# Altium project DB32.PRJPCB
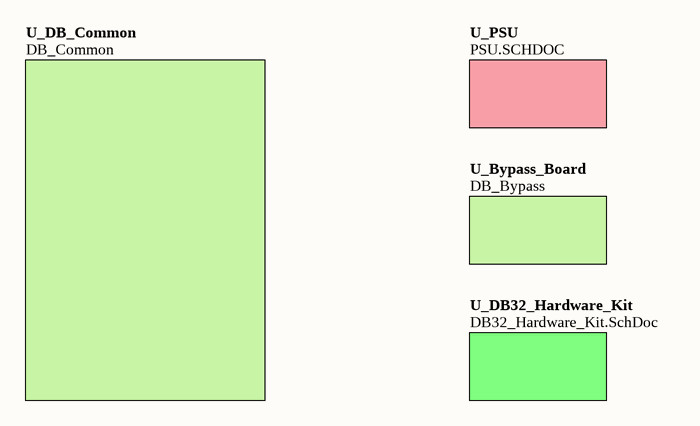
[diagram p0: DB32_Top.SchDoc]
ProjectAddress1: L3, 12A Rodborough Road; ProjectAddress2: Frenchs Forest; ProjectAddress3: NSW 2086; ProjectAddress4: Australia; ProjectAssyNum: D-820-0006; ProjectOrganization: Altium Limited; ProjectRevision: 08; ProjectTitle: DB32 - Daughter Board Lattice; ProjectTotalSheets: 19
8 sheets, 129 parts. Net scope: hierarchical (ports join the sheet entries above them; power ports are global).
Board files: DB32.PcbDoc, DB32_Panel.PcbDoc
Sheets:
  DB32_Top.SchDoc
    U_PSU = PSU.SCHDOC
    U_DB32_Hardware_Kit = DB32_Hardware_Kit.SchDoc
  DEVICES.SchDoc
    U_FPGA = FPGA.SCHDOC
      U_FPGA_Power = FPGA_NonIO.SchDoc
      U_Bypass_3V3 = Bypass_FPGA_3V3.SchDoc
      U_Bypass_1V2 = Bypass_FPGA_1V2.SCHDOC

## Sheet DB32_Top.SchDoc: DB32 Top Level
size A4; Organization: Altium Limited.; Address1: Level 3, 12a Rodborough Rd; Address2: Frenchs Forest 2086; Address3: NSW; Address4: AUSTRALIA; DocumentNumber: 1; SheetNumber: 2; SheetTotal: 21

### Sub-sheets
U_Bypass_Board = DB_Bypass (file not in this document): no entries
U_DB32_Hardware_Kit = DB32_Hardware_Kit.SchDoc: no entries
U_DB_Common = DB_Common (file not in this document): no entries
U_PSU = PSU.SCHDOC: no entries

## Sheet PSU.SCHDOC: Power Supply Top Level
size A4; Organization: Altium Limited.; Address1: Level 3, 12a Rodborough Rd; Address2: Frenchs Forest 2086; Address3: NSW; Address4: AUSTRALIA; DocumentNumber: 9; SheetNumber: 9; SheetTotal: 21
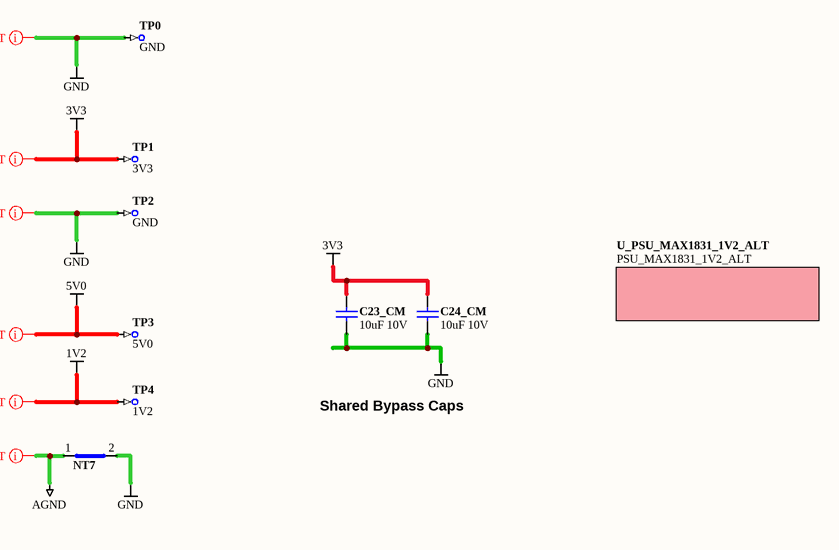
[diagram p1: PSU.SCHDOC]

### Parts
C23_CM  10uF 10V  [CAPC2012-STAR]
C24_CM  10uF 10V  [CAPC2012-STAR]
NT7  Net Tie SMT2  [NETTIE-SMT2-8X8]  (value not drawn)  (net tie, no BOM)
TP0  GND  [TestPin]  (no BOM)
TP1  3V3  [TestPin]  (no BOM)
TP2  GND  [TestPin]  (no BOM)
TP3  5V0  [TestPin]  (no BOM)
TP4  1V2  [TestPin]  (no BOM)

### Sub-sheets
U_PSU_MAX1831_1V2_ALT = PSU_MAX1831_1V2_ALT (file not in this document): no entries

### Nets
1V2: TP4.1
3V3: C23_CM.1 C24_CM.1 TP1.1
5V0: TP3.1
AGND: NT7.1(Net1)
GND: C23_CM.2 C24_CM.2 NT7.2(Net2) TP0.1 TP2.1

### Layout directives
net class PWRNET: 1V2, 3V3, 5V0, AGND, GND

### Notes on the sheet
- Shared Bypass Caps

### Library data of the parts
C23_CM C24_CM = D-101-0087: Capacitor, Ceramic, 10uF 10% 10V 0805 (2012) X5R; Polarity: Non-Polarized
NT7 = D-002-0002: Net-Tie, Surface Mount, 2 x 0.4mm x 0.2mm SMT Pads - For 0.2mm Track
TP0-TP4 = D-006-0000: Test Point, PCB Mount with Silkscreen Box

## Sheet DB32_Hardware_Kit.SchDoc: DB32 Hardware Kit
size A4; Organization: Altium Limited.; Address1: Level 3, 12a Rodborough Rd; Address2: Frenchs Forest 2086; Address3: NSW; Address4: AUSTRALIA; DocumentNumber: 8; SheetNumber: 8; SheetTotal: 21
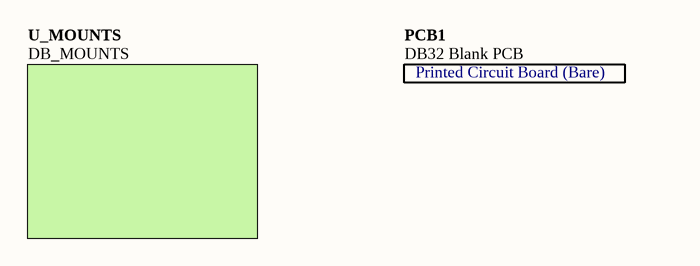
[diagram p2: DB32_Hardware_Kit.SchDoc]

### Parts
PCB1  DB32 Blank PCB  (mechanical)

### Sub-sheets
U_MOUNTS = DB_MOUNTS (file not in this document): no entries

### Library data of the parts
PCB1 = D-810-0006: DB32 Blank PCB - Daughter Board Lattice ECP LFECP33E-3FN672C; ProjectPath: DB32.PrjPCB

## Sheet DEVICES.SchDoc: FPGA, LEDs and SRAM Memory
size A4; Organization: Altium Limited.; Address1: Level 3, 12a Rodborough Rd; Address2: Frenchs Forest 2086; Address3: NSW; Address4: AUSTRALIA; DocumentNumber: 2; SheetNumber: 3; SheetTotal: 21
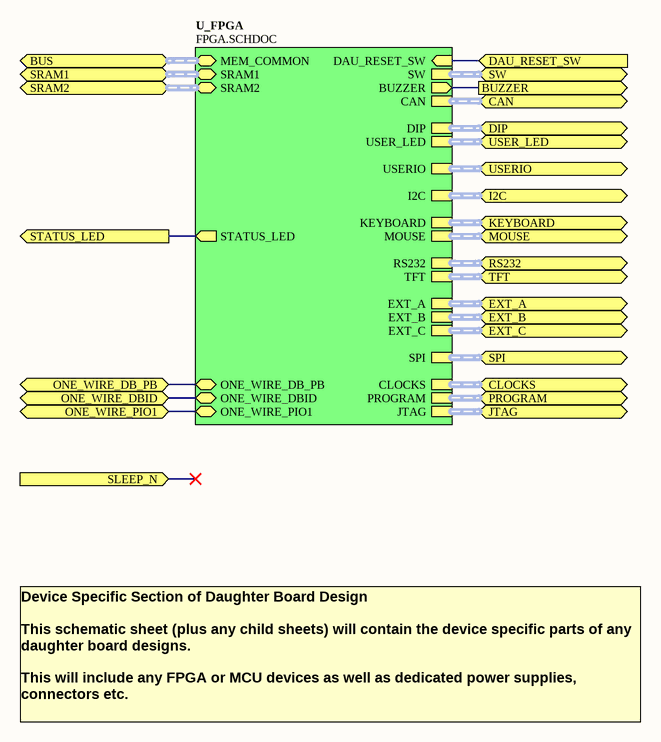
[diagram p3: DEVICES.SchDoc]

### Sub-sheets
U_FPGA = FPGA.SCHDOC: SRAM1 (harness SRAM-256Kx16), SRAM2 (harness SRAM-256Kx16), MEM_COMMON (harness HOSTMEMORY), DAU_RESET_SW (in), BUZZER (out), ONE_WIRE_DBID (bidir), ONE_WIRE_DB_PB (bidir), ONE_WIRE_PIO1 (bidir), JTAG (harness HardSoft_JTAG), SW (harness SW5), DIP (harness SW8), USERIO (harness IO36), EXT_A (harness PBIO), EXT_B (harness PBIO), EXT_C (harness PBIO), USER_LED (harness LED8), SPI (harness DAU_SPI), I2C (harness I2C), CAN (harness CAN_INT), RS232 (harness RS232_INT), KEYBOARD (harness PS2), MOUSE (harness PS2), TFT (harness DAU_TFT), PROGRAM (harness DAU_CTRL), CLOCKS (harness DAU_CLK), STATUS_LED (out)

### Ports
BUS (harness HOSTMEMORY), BUZZER (out), CAN, CLOCKS, DAU_RESET_SW (in), DIP, EXT_A, EXT_B, EXT_C, I2C, JTAG, KEYBOARD, MOUSE, ONE_WIRE_DB_PB (bidir), ONE_WIRE_DBID (bidir), ONE_WIRE_PIO1 (bidir), PROGRAM, RS232, SLEEP_N (in), SPI, SRAM1, SRAM2 (harness SRAM-256Kx16), STATUS_LED (out), SW, TFT, USER_LED, USERIO

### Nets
BUZZER: port BUZZER, sheet U_FPGA/BUZZER
DAU_RESET_SW: port DAU_RESET_SW, sheet U_FPGA/DAU_RESET_SW
ONE_WIRE_DB_PB: port ONE_WIRE_DB_PB, sheet U_FPGA/ONE_WIRE_DB_PB
ONE_WIRE_DBID: port ONE_WIRE_DBID, sheet U_FPGA/ONE_WIRE_DBID
ONE_WIRE_PIO1: port ONE_WIRE_PIO1, sheet U_FPGA/ONE_WIRE_PIO1
STATUS_LED: port STATUS_LED, sheet U_FPGA/STATUS_LED

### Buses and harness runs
harness port BUS = sheet U_FPGA/MEM_COMMON
harness port CAN = sheet U_FPGA/CAN
harness port CLOCKS = sheet U_FPGA/CLOCKS
harness port DIP = sheet U_FPGA/DIP
harness port EXT_A = sheet U_FPGA/EXT_A
harness port EXT_B = sheet U_FPGA/EXT_B
harness port EXT_C = sheet U_FPGA/EXT_C
harness port I2C = sheet U_FPGA/I2C
harness port JTAG = sheet U_FPGA/JTAG
harness port KEYBOARD = sheet U_FPGA/KEYBOARD
harness port MOUSE = sheet U_FPGA/MOUSE
harness port PROGRAM = sheet U_FPGA/PROGRAM
harness port RS232 = sheet U_FPGA/RS232
harness port SPI = sheet U_FPGA/SPI
harness port SRAM1 = sheet U_FPGA/SRAM1
harness port SRAM2 = sheet U_FPGA/SRAM2
harness port SW = sheet U_FPGA/SW
harness port TFT = sheet U_FPGA/TFT
harness port USER_LED = sheet U_FPGA/USER_LED
harness port USERIO = sheet U_FPGA/USERIO

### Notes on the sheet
- Device Specific Section of Daughter Board Design
  This schematic sheet (plus any child sheets) will contain the device specific parts of any daughter board designs.
  This will include any FPGA or MCU devices as well as dedicated power supplies, connectors etc.

## Sheet FPGA.SCHDOC: FPGA Connections
size A2; Organization: Altium Limited.; Address1: Level 3, 12a Rodborough Rd; Address2: Frenchs Forest 2086; Address3: NSW; Address4: AUSTRALIA; DocumentNumber: 3; SheetNumber: 4; SheetTotal: 21; PageSetup: Record=PageOptions|CenterHorizontal=True|CenterVertical=True|PrintScale=0.49|XCorrection=1.00|YCorrection=1.00|PrintKind=2|BorderSize=5000000|LeftOffset=0|BottomOffset=0|Orientation=2|PaperLength=1000|PaperWidth=1000|Scale=100|PaperSource=15|PrintQuality=600|MediaType=1|DitherType=10|PaperKind=A4|PrintScaleMode=1
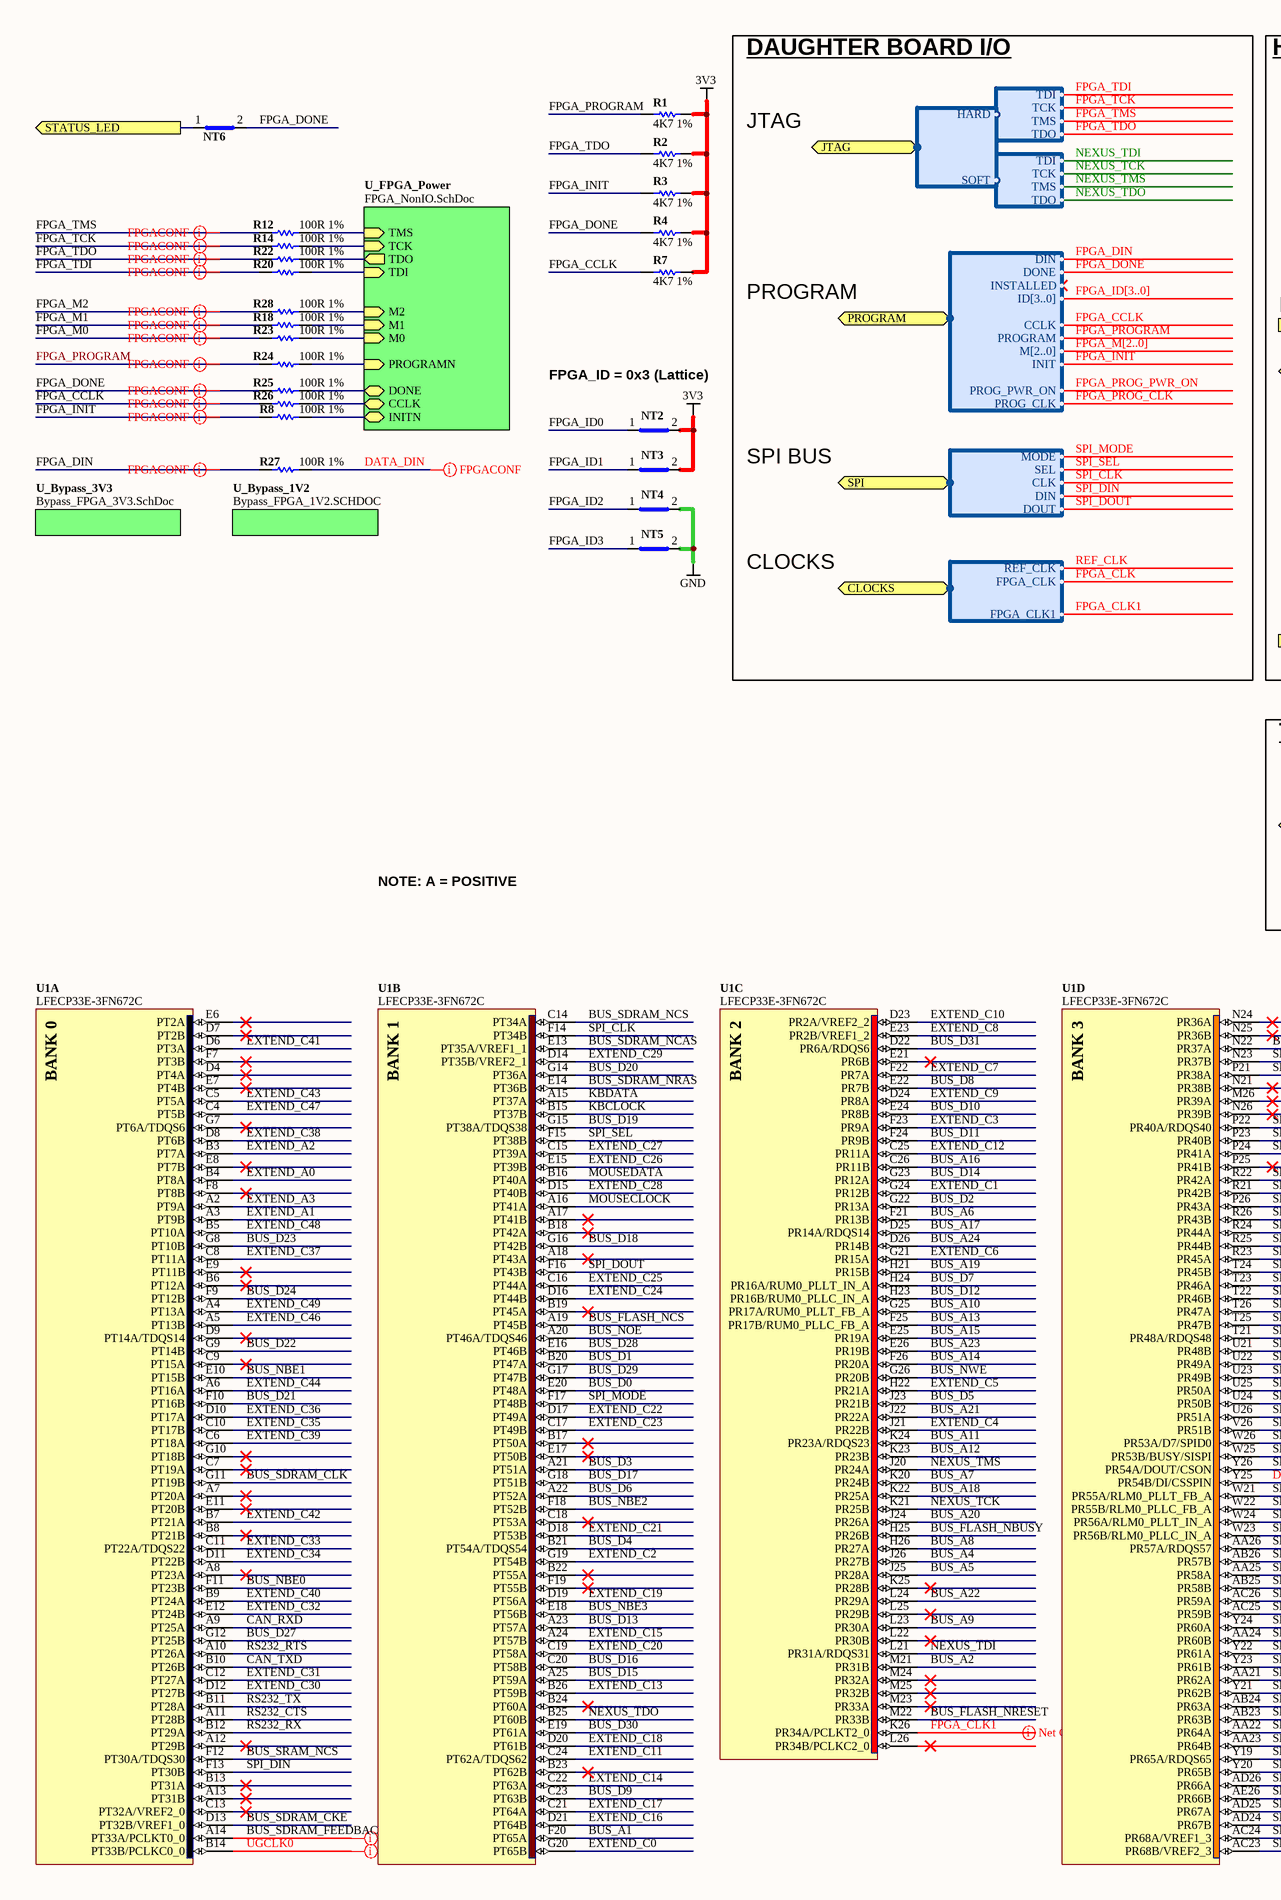
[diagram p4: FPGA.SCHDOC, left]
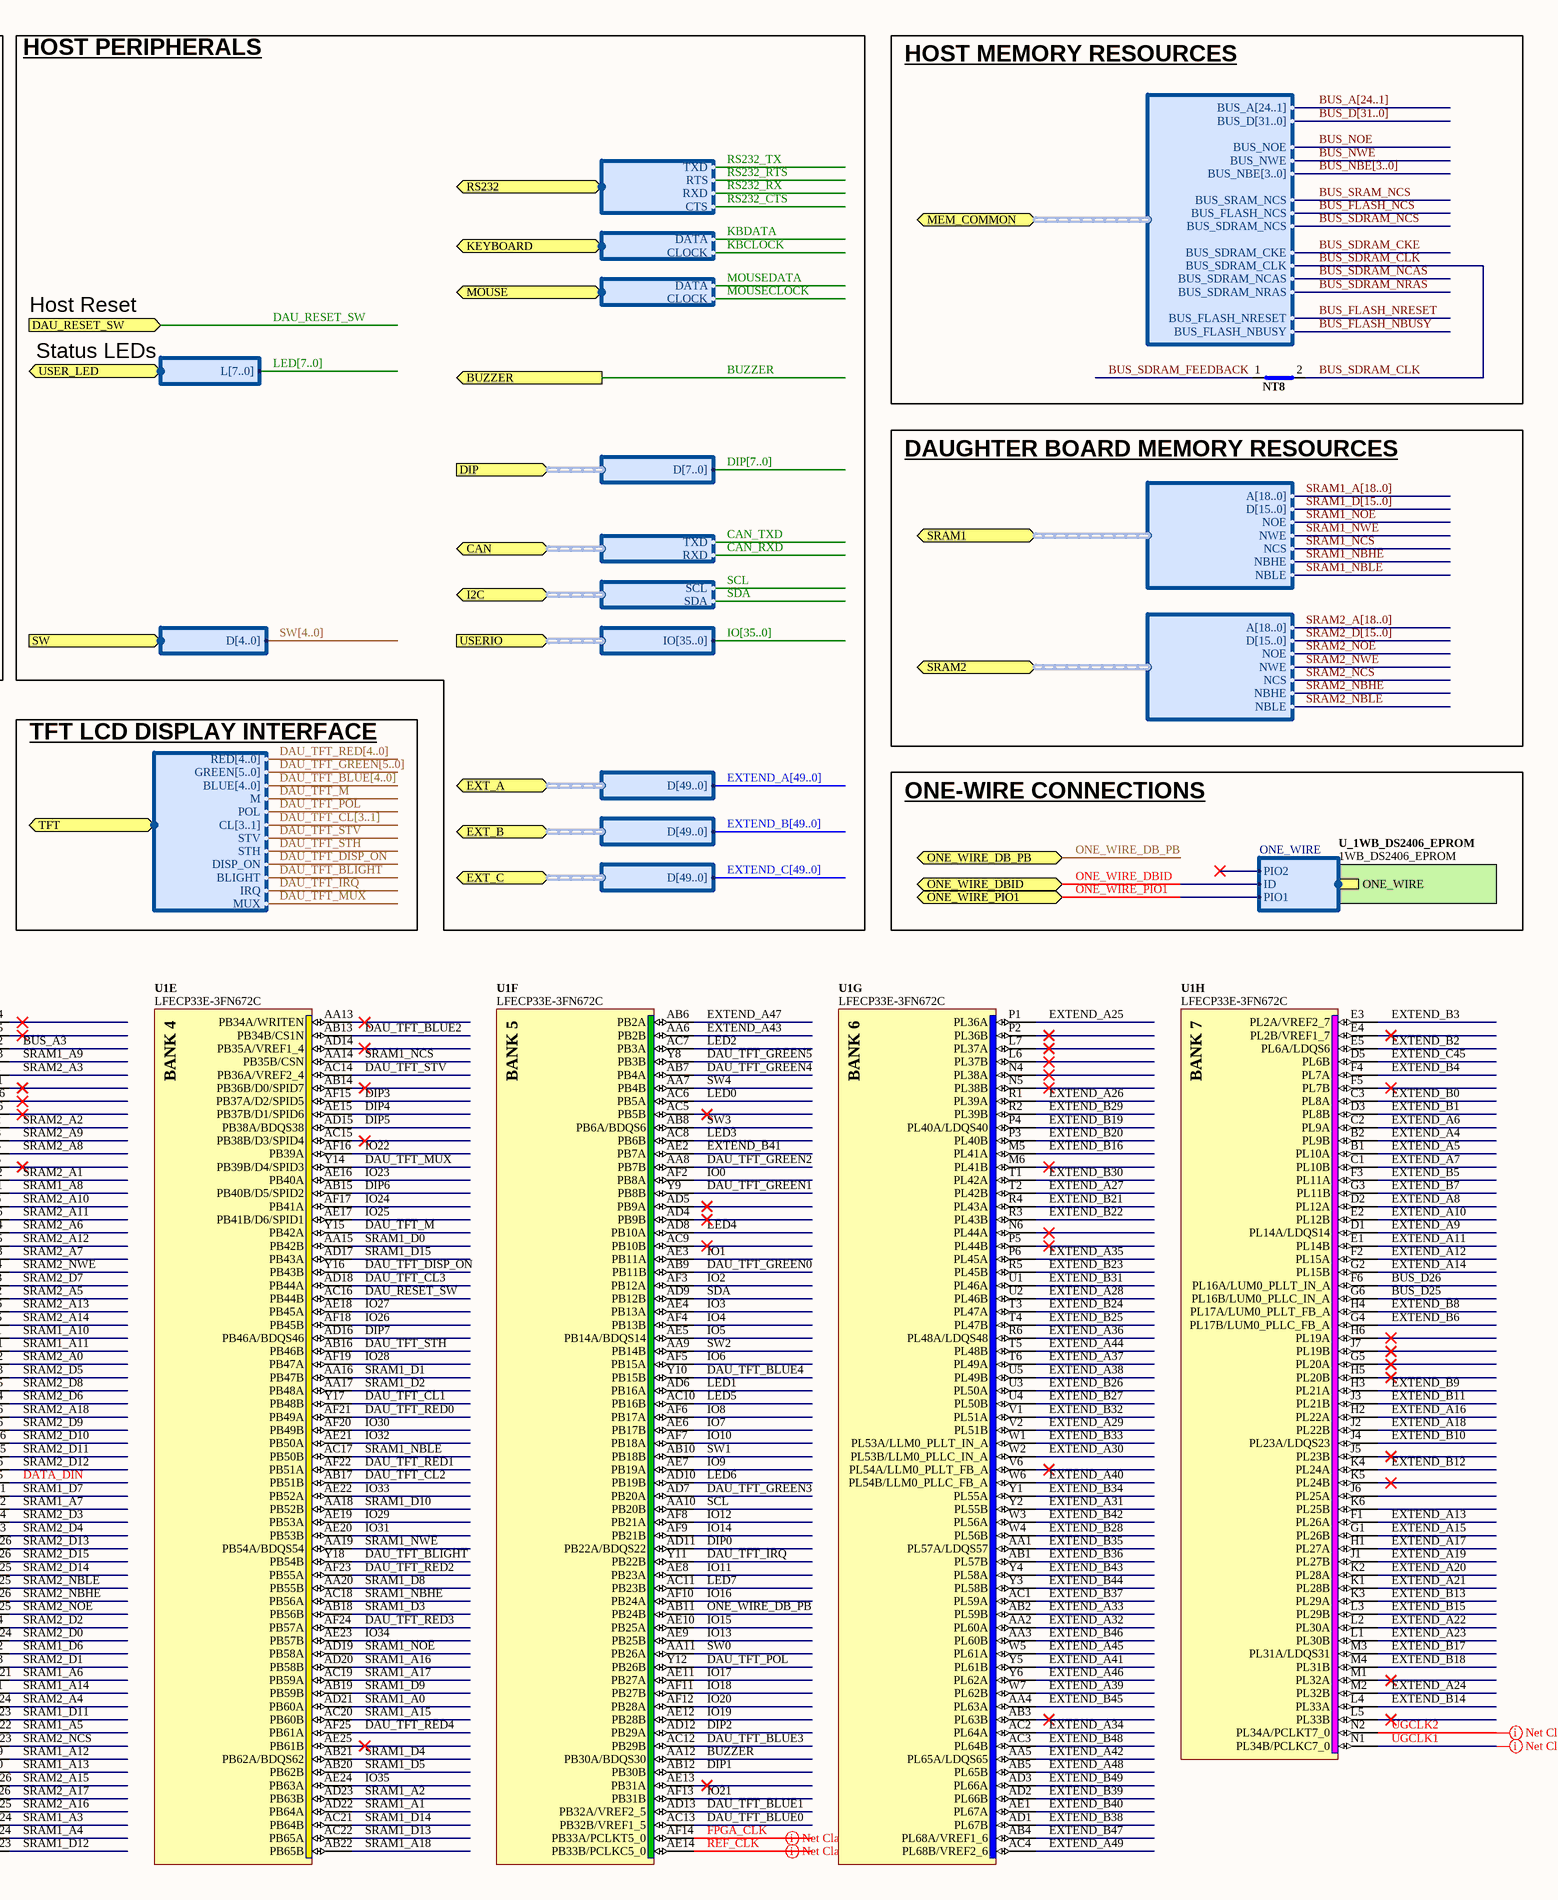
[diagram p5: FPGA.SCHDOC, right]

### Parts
NT2  Net Tie SMT2  [NETTIE-SMT2-8X8]  (value not drawn)  (net tie, no BOM)
NT3  Net Tie SMT2  [NETTIE-SMT2-8X8]  (value not drawn)  (net tie, no BOM)
NT4  Net Tie SMT2  [NETTIE-SMT2-8X8]  (value not drawn)  (net tie, no BOM)
NT5  Net Tie SMT2  [NETTIE-SMT2-8X8]  (value not drawn)  (net tie, no BOM)
NT6  Net Tie SMT2  [NETTIE-SMT2-8X8]  (value not drawn)  (net tie, no BOM)
NT8  Net Tie SMT2  [NETTIE-SMT2-8X8]  (value not drawn)  (net tie, no BOM)
R1  4K7 1%  [RESC1005-STAR]
R2  4K7 1%  [RESC1005-STAR]
R3  4K7 1%  [RESC1005-STAR]
R4  4K7 1%  [RESC1005-STAR]
R7  4K7 1%  [RESC1005-STAR]
R8  100R 1%  [RESC1005-STAR]
R12  100R 1%  [RESC1005-STAR]
R14  100R 1%  [RESC1005-STAR]
R18  100R 1%  [RESC1005-STAR]
R20  100R 1%  [RESC1005-STAR]
R22  100R 1%  [RESC1005-STAR]
R23  100R 1%  [RESC1005-STAR]
R24  100R 1%  [RESC1005-STAR]
R25  100R 1%  [RESC1005-STAR]
R26  100R 1%  [RESC1005-STAR]
R27  100R 1%  [RESC1005-STAR]
R28  100R 1%  [RESC1005-STAR]
U1  LFECP33E-3FN672C  [BGA100P26X26-672]  (parts A,B,C,D,E,F,G,H of 12)

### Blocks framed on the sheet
HOST MEMORY RESOURCES: NT8

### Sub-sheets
U_1WB_DS2406_EPROM = 1WB_DS2406_EPROM (file not in this document): ONE_WIRE (harness ONE_WIRE)
U_Bypass_1V2 = Bypass_FPGA_1V2.SCHDOC: no entries
U_Bypass_3V3 = Bypass_FPGA_3V3.SchDoc: no entries
U_FPGA_Power = FPGA_NonIO.SchDoc: TMS (in), DONE (bidir), M1 (in), CCLK (bidir), M0 (in), M2 (in), TCK (in), INITN (bidir), TDI (in), PROGRAMN (in), TDO (out)

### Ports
BUZZER (out), CAN (harness CAN_INT), CLOCKS (harness DAU_CLK), DAU_RESET_SW (in), DIP (harness SW8), EXT_A (harness PBIO), EXT_B (harness PBIO), EXT_C (harness PBIO), I2C (harness I2C), JTAG (harness HARDSOFT_JTAG), KEYBOARD (harness PS2), MEM_COMMON (harness HOSTMEMORY), MOUSE (harness PS2), ONE_WIRE_DB_PB (bidir), ONE_WIRE_DBID (bidir), ONE_WIRE_PIO1 (bidir), PROGRAM (harness DAU_CTRL), RS232 (harness RS232_INT), SPI (harness DAU_SPI), SRAM1 (harness SRAM-256Kx16), SRAM2 (harness SRAM-256Kx16), STATUS_LED (out), SW (harness SW5), TFT (harness DAU_TFT), USER_LED (harness LED8), USERIO (harness IO36)

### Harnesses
ONE_WIRE: ID, PIO1, PIO2
SRAM-256Kx16: A[18..0], D[15..0], NCS, NWE, NOE, NBHE, NBLE
HOSTMEMORY: BUS_A[24..1], BUS_D[31..0], BUS_NOE, BUS_NWE, BUS_NBE[3..0], BUS_SRAM_NCS, BUS_FLASH_NCS, BUS_SDRAM_NCS, BUS_SDRAM_CKE, BUS_SDRAM_CLK, BUS_SDRAM_NCAS, BUS_SDRAM_NRAS, BUS_FLASH_NRESET, BUS_FLASH_NBUSY
DAU_CLK: REF_CLK, FPGA_CLK, FPGA_CLK1
DAU_SPI: MODE, SEL, CLK, DIN, DOUT
DAU_CTRL: DIN, DONE, INSTALLED, ID[3..0], CCLK, PROGRAM, M[2..0], INIT, PROG_PWR_ON, PROG_CLK
JTAG: TMS, TDO, TDI, TCK
HARDSOFT_JTAG: HARD, SOFT
LED8: L[7..0]
SW5: D[4..0]
DAU_TFT: RED[4..0], GREEN[5..0], BLUE[4..0], M, POL, CL[3..1], STV, STH, DISP_ON, BLIGHT, IRQ, MUX
PS2: DATA, CLOCK
RS232_INT: RXD, TXD, RTS, CTS
IO36: IO[35..0]
SW8: D[7..0]
CAN_INT: TXD, RXD
I2C: SCL, SDA
PBIO: D[49..0]

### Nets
3V3: NT2.2(Net2) NT3.2(Net2) R1.2 R2.2 R3.2 R4.2 R7.2
GND: NT4.2(Net2) NT5.2(Net2)
BUS_A1: U1.F20(PT65A)
BUS_A2: U1.M21(PR31B)
BUS_A3: U1.N22(PR37A)
BUS_A4: U1.J26(PR27B)
BUS_A5: U1.J25(PR28A)
BUS_A6: U1.F21(PR13B)
BUS_A7: U1.K20(PR24B)
BUS_A8: U1.H26(PR27A)
BUS_A9: U1.L23(PR30A)
BUS_A10: U1.G25(PR17A/RUM0_PLLT_FB_A)
BUS_A11: U1.K24(PR23A/RDQS23)
BUS_A12: U1.K23(PR23B)
BUS_A13: U1.F25(PR17B/RUM0_PLLC_FB_A)
BUS_A14: U1.F26(PR20A)
BUS_A15: U1.E25(PR19A)
BUS_A16: U1.C26(PR11B)
BUS_A17: U1.D25(PR14A/RDQS14)
BUS_A18: U1.K22(PR25A)
BUS_A19: U1.H21(PR15B)
BUS_A20: U1.J24(PR26A)
BUS_A21: U1.J22(PR22A)
BUS_A22: U1.L24(PR29A)
BUS_A23: U1.E26(PR19B)
BUS_A24: U1.D26(PR14B)
BUS_D0: U1.E20(PT48A)
BUS_D1: U1.B20(PT47A)
BUS_D2: U1.G22(PR13A)
BUS_D3: U1.A21(PT51A)
BUS_D4: U1.B21(PT54A/TDQS54)
BUS_D5: U1.J23(PR21B)
BUS_D6: U1.A22(PT52A)
BUS_D7: U1.H24(PR16A/RUM0_PLLT_IN_A)
BUS_D8: U1.E22(PR7B)
BUS_D9: U1.C23(PT63B)
BUS_D10: U1.E24(PR8B)
BUS_D11: U1.F24(PR9B)
BUS_D12: U1.H23(PR16B/RUM0_PLLC_IN_A)
BUS_D13: U1.A23(PT57A)
BUS_D14: U1.G23(PR12A)
BUS_D15: U1.A25(PT59A)
BUS_D16: U1.C20(PT58B)
BUS_D17: U1.G18(PT51B)
BUS_D18: U1.G16(PT42B)
BUS_D19: U1.G15(PT38A/TDQS38)
BUS_D20: U1.G14(PT36A)
BUS_D21: U1.F10(PT16B)
BUS_D22: U1.G9(PT14B)
BUS_D23: U1.G8(PT10B)
BUS_D24: U1.F9(PT12B)
BUS_D25: U1.G6(PL16B/LUM0_PLLC_IN_A)
BUS_D26: U1.F6(PL16A/LUM0_PLLT_IN_A)
BUS_D27: U1.G12(PT25B)
BUS_D28: U1.E16(PT46B)
BUS_D29: U1.G17(PT47B)
BUS_D30: U1.E19(PT61A)
BUS_D31: U1.D22(PR6A/RDQS6)
BUS_FLASH_NBUSY: U1.H25(PR26B) ; port MEM_COMMON.BUS_FLASH_NBUSY
BUS_FLASH_NCS: U1.A19(PT45B) ; port MEM_COMMON.BUS_FLASH_NCS
BUS_FLASH_NRESET: U1.M22(PR33B) ; port MEM_COMMON.BUS_FLASH_NRESET
BUS_NBE0: U1.F11(PT23B)
BUS_NBE1: U1.E10(PT15B)
BUS_NBE2: U1.F18(PT52B)
BUS_NBE3: U1.E18(PT56B)
BUS_NOE: U1.A20(PT46A/TDQS46) ; port MEM_COMMON.BUS_NOE
BUS_NWE: U1.G26(PR20B) ; port MEM_COMMON.BUS_NWE
BUS_SDRAM_CKE: U1.D13(PT32B/VREF1_0) ; port MEM_COMMON.BUS_SDRAM_CKE
BUS_SDRAM_CLK: NT8.2(Net2) U1.G11(PT19B) ; port MEM_COMMON.BUS_SDRAM_CLK
BUS_SDRAM_FEEDBACK: NT8.1(Net1) U1.A14(PT33A/PCLKT0_0)
BUS_SDRAM_NCAS: U1.E13(PT35A/VREF1_1) ; port MEM_COMMON.BUS_SDRAM_NCAS
BUS_SDRAM_NCS: U1.C14(PT34A) ; port MEM_COMMON.BUS_SDRAM_NCS
BUS_SDRAM_NRAS: U1.E14(PT36B) ; port MEM_COMMON.BUS_SDRAM_NRAS
BUS_SRAM_NCS: U1.F12(PT30A/TDQS30) ; port MEM_COMMON.BUS_SRAM_NCS
BUZZER: U1.AA12(PB30A/BDQS30) ; port BUZZER
CAN_RXD: U1.A9(PT25A) ; port CAN.RXD
CAN_TXD: U1.B10(PT26B) ; port CAN.TXD
CCLK: R26.2 ; sheet U_FPGA_Power/CCLK
DATA_DIN: R27.2 U1.Y25(PR54B/DI/CSSPIN)
DAU_RESET_SW: U1.AC16(PB44B) ; port DAU_RESET_SW
DAU_TFT_BLIGHT: U1.Y18(PB54B) ; port TFT.BLIGHT
DAU_TFT_BLUE0: U1.AC13(PB32B/VREF1_5)
DAU_TFT_BLUE1: U1.AD13(PB32A/VREF2_5)
DAU_TFT_BLUE2: U1.AB13(PB34B/CS1N)
DAU_TFT_BLUE3: U1.AC12(PB29B)
DAU_TFT_BLUE4: U1.Y10(PB15B)
DAU_TFT_CL1: U1.Y17(PB48B)
DAU_TFT_CL2: U1.AB17(PB51B)
DAU_TFT_CL3: U1.AD18(PB44A)
DAU_TFT_DISP_ON: U1.Y16(PB43B) ; port TFT.DISP_ON
DAU_TFT_GREEN0: U1.AB9(PB11B)
DAU_TFT_GREEN1: U1.Y9(PB8B)
DAU_TFT_GREEN2: U1.AA8(PB7B)
DAU_TFT_GREEN3: U1.AD7(PB20A)
DAU_TFT_GREEN4: U1.AB7(PB4A)
DAU_TFT_GREEN5: U1.Y8(PB3B)
DAU_TFT_IRQ: U1.Y11(PB22B) ; port TFT.IRQ
DAU_TFT_M: U1.Y15(PB42A) ; port TFT.M
DAU_TFT_MUX: U1.Y14(PB39B/D4/SPID3) ; port TFT.MUX
DAU_TFT_POL: U1.Y12(PB26B) ; port TFT.POL
DAU_TFT_RED0: U1.AF21(PB49A)
DAU_TFT_RED1: U1.AF22(PB51A)
DAU_TFT_RED2: U1.AF23(PB55A)
DAU_TFT_RED3: U1.AF24(PB57A)
DAU_TFT_RED4: U1.AF25(PB61A)
DAU_TFT_STH: U1.AB16(PB46B) ; port TFT.STH
DAU_TFT_STV: U1.AC14(PB36A/VREF2_4) ; port TFT.STV
DIP0: U1.AD11(PB22A/BDQS22)
DIP1: U1.AB12(PB30B)
DIP2: U1.AD12(PB29A)
DIP3: U1.AF15(PB37A/D2/SPID5)
DIP4: U1.AE15(PB37B/D1/SPID6)
DIP5: U1.AD15(PB38A/BDQS38)
DIP6: U1.AB15(PB40B/D5/SPID2)
DIP7: U1.AD16(PB46A/BDQS46)
DONE: R25.2 ; sheet U_FPGA_Power/DONE
EXTEND_A0: U1.B4(PT8A)
EXTEND_A1: U1.A3(PT9B)
EXTEND_A2: U1.B3(PT7A)
EXTEND_A3: U1.A2(PT9A)
EXTEND_A4: U1.B2(PL9B)
EXTEND_A5: U1.B1(PL10A)
EXTEND_A6: U1.C2(PL9A)
EXTEND_A7: U1.C1(PL10B)
EXTEND_A8: U1.D2(PL12A)
EXTEND_A9: U1.D1(PL14A/LDQS14)
EXTEND_A10: U1.E2(PL12B)
EXTEND_A11: U1.E1(PL14B)
EXTEND_A12: U1.F2(PL15A)
EXTEND_A13: U1.F1(PL26A)
EXTEND_A14: U1.G2(PL15B)
EXTEND_A15: U1.G1(PL26B)
EXTEND_A16: U1.H2(PL22A)
EXTEND_A17: U1.H1(PL27A)
EXTEND_A18: U1.J2(PL22B)
EXTEND_A19: U1.J1(PL27B)
EXTEND_A20: U1.K2(PL28A)
EXTEND_A21: U1.K1(PL28B)
EXTEND_A22: U1.L2(PL30A)
EXTEND_A23: U1.L1(PL30B)
EXTEND_A24: U1.M2(PL32B)
EXTEND_A25: U1.P1(PL36A)
EXTEND_A26: U1.R1(PL39A)
EXTEND_A27: U1.T2(PL42B)
EXTEND_A28: U1.U2(PL46B)
EXTEND_A29: U1.V2(PL51B)
EXTEND_A30: U1.W2(PL53B/LLM0_PLLC_IN_A)
EXTEND_A31: U1.Y2(PL55B)
EXTEND_A32: U1.AA2(PL60A)
EXTEND_A33: U1.AB2(PL59B)
EXTEND_A34: U1.AC2(PL64A)
EXTEND_A35: U1.P6(PL45A)
EXTEND_A36: U1.R6(PL48A/LDQS48)
EXTEND_A37: U1.T6(PL49A)
EXTEND_A38: U1.U5(PL49B)
EXTEND_A39: U1.W7(PL62B)
EXTEND_A40: U1.W6(PL54B/LLM0_PLLC_FB_A)
EXTEND_A41: U1.Y5(PL61B)
EXTEND_A42: U1.AA5(PL65A/LDQS65)
EXTEND_A43: U1.AA6(PB2B)
EXTEND_A44: U1.T5(PL48B)
EXTEND_A45: U1.W5(PL61A)
EXTEND_A46: U1.Y6(PL62A)
EXTEND_A47: U1.AB6(PB2A)
EXTEND_A48: U1.AB5(PL65B)
EXTEND_A49: U1.AC4(PL68B/VREF2_6)
EXTEND_B0: U1.C3(PL8A)
EXTEND_B1: U1.D3(PL8B)
EXTEND_B2: U1.E5(PL6A/LDQS6)
EXTEND_B3: U1.E3(PL2A/VREF2_7)
EXTEND_B4: U1.F4(PL7A)
EXTEND_B5: U1.F3(PL11A)
EXTEND_B6: U1.G4(PL17B/LUM0_PLLC_FB_A)
EXTEND_B7: U1.G3(PL11B)
EXTEND_B8: U1.H4(PL17A/LUM0_PLLT_FB_A)
EXTEND_B9: U1.H3(PL21A)
EXTEND_B10: U1.J4(PL23A/LDQS23)
EXTEND_B11: U1.J3(PL21B)
EXTEND_B12: U1.K4(PL24A)
EXTEND_B13: U1.K3(PL29A)
EXTEND_B14: U1.L4(PL33A)
EXTEND_B15: U1.L3(PL29B)
EXTEND_B16: U1.M5(PL41A)
EXTEND_B17: U1.M3(PL31A/LDQS31)
EXTEND_B18: U1.M4(PL31B)
EXTEND_B19: U1.P4(PL40A/LDQS40)
EXTEND_B20: U1.P3(PL40B)
EXTEND_B21: U1.R4(PL43A)
EXTEND_B22: U1.R3(PL43B)
EXTEND_B23: U1.R5(PL45B)
EXTEND_B24: U1.T3(PL47A)
EXTEND_B25: U1.T4(PL47B)
EXTEND_B26: U1.U3(PL50A)
EXTEND_B27: U1.U4(PL50B)
EXTEND_B28: U1.W4(PL56B)
EXTEND_B29: U1.R2(PL39B)
EXTEND_B30: U1.T1(PL42A)
EXTEND_B31: U1.U1(PL46A)
EXTEND_B32: U1.V1(PL51A)
EXTEND_B33: U1.W1(PL53A/LLM0_PLLT_IN_A)
EXTEND_B34: U1.Y1(PL55A)
EXTEND_B35: U1.AA1(PL57A/LDQS57)
EXTEND_B36: U1.AB1(PL57B)
EXTEND_B37: U1.AC1(PL59A)
EXTEND_B38: U1.AD1(PL67B)
EXTEND_B39: U1.AD2(PL66B)
EXTEND_B40: U1.AE1(PL67A)
EXTEND_B41: U1.AE2(PB7A)
EXTEND_B42: U1.W3(PL56A)
EXTEND_B43: U1.Y4(PL58A)
EXTEND_B44: U1.Y3(PL58B)
EXTEND_B45: U1.AA4(PL63A)
EXTEND_B46: U1.AA3(PL60B)
EXTEND_B47: U1.AB4(PL68A/VREF1_6)
EXTEND_B48: U1.AC3(PL64B)
EXTEND_B49: U1.AD3(PL66A)
EXTEND_C0: U1.G20(PT65B)
EXTEND_C1: U1.G24(PR12B)
EXTEND_C2: U1.G19(PT54B)
EXTEND_C3: U1.F23(PR9A)
EXTEND_C4: U1.J21(PR22B)
EXTEND_C5: U1.H22(PR21A)
EXTEND_C6: U1.G21(PR15A)
EXTEND_C7: U1.F22(PR7A)
EXTEND_C8: U1.E23(PR2B/VREF1_2)
EXTEND_C9: U1.D24(PR8A)
EXTEND_C10: U1.D23(PR2A/VREF2_2)
EXTEND_C11: U1.C24(PT62A/TDQS62)
EXTEND_C12: U1.C25(PR11A)
EXTEND_C13: U1.B26(PT59B)
EXTEND_C14: U1.C22(PT63A)
EXTEND_C15: U1.A24(PT57B)
EXTEND_C16: U1.D21(PT64B)
EXTEND_C17: U1.C21(PT64A)
EXTEND_C18: U1.D20(PT61B)
EXTEND_C19: U1.D19(PT56A)
EXTEND_C20: U1.C19(PT58A)
EXTEND_C21: U1.D18(PT53B)
EXTEND_C22: U1.D17(PT49A)
EXTEND_C23: U1.C17(PT49B)
EXTEND_C24: U1.D16(PT44B)
EXTEND_C25: U1.C16(PT44A)
EXTEND_C26: U1.E15(PT39B)
EXTEND_C27: U1.C15(PT39A)
EXTEND_C28: U1.D15(PT40B)
EXTEND_C29: U1.D14(PT35B/VREF2_1)
EXTEND_C30: U1.D12(PT27B)
EXTEND_C31: U1.C12(PT27A)
EXTEND_C32: U1.E12(PT24B)
EXTEND_C33: U1.C11(PT22A/TDQS22)
EXTEND_C34: U1.D11(PT22B)
EXTEND_C35: U1.C10(PT17B)
EXTEND_C36: U1.D10(PT17A)
EXTEND_C37: U1.C8(PT11A)
EXTEND_C38: U1.D8(PT6B)
EXTEND_C39: U1.C6(PT18A)
EXTEND_C40: U1.B9(PT24A)
EXTEND_C41: U1.D6(PT3A)
EXTEND_C42: U1.B7(PT21A)
EXTEND_C43: U1.C5(PT5A)
EXTEND_C44: U1.A6(PT16A)
EXTEND_C45: U1.D5(PL6B)
EXTEND_C46: U1.A5(PT13B)
EXTEND_C47: U1.C4(PT5B)
EXTEND_C48: U1.B5(PT10A)
EXTEND_C49: U1.A4(PT13A)
FPGA_CCLK: R7.1 R26.1 ; port PROGRAM.CCLK
FPGA_CLK: U1.AF14(PB33A/PCLKT5_0) ; port CLOCKS.FPGA_CLK
FPGA_CLK1: U1.K26(PR34A/PCLKT2_0) ; port CLOCKS.FPGA_CLK1
FPGA_DIN: R27.1 ; port PROGRAM.DIN
FPGA_DONE: NT6.2(Net2) R4.1 R25.1 ; port PROGRAM.DONE
FPGA_ID0: NT2.1(Net1)
FPGA_ID1: NT3.1(Net1)
FPGA_ID2: NT4.1(Net1)
FPGA_ID3: NT5.1(Net1)
FPGA_INIT: R3.1 R8.1 ; port PROGRAM.INIT
FPGA_M0: R23.1
FPGA_M1: R18.1
FPGA_M2: R28.1
FPGA_PROGRAM: R1.1 R24.1 ; port PROGRAM.PROGRAM
FPGA_TCK: R14.1 ; harness JTAG.TCK
FPGA_TDI: R20.1 ; harness JTAG.TDI
FPGA_TDO: R2.1 R22.1 ; harness JTAG.TDO
FPGA_TMS: R12.1 ; harness JTAG.TMS
INITN: R8.2 ; sheet U_FPGA_Power/INITN
IO0: U1.AF2(PB8A)
IO1: U1.AE3(PB11A)
IO2: U1.AF3(PB12A)
IO3: U1.AE4(PB13A)
IO4: U1.AF4(PB13B)
IO5: U1.AE5(PB14A/BDQS14)
IO6: U1.AF5(PB15A)
IO7: U1.AE6(PB17B)
IO8: U1.AF6(PB17A)
IO9: U1.AE7(PB19A)
IO10: U1.AF7(PB18A)
IO11: U1.AE8(PB23A)
IO12: U1.AF8(PB21A)
IO13: U1.AE9(PB25B)
IO14: U1.AF9(PB21B)
IO15: U1.AE10(PB25A)
IO16: U1.AF10(PB24A)
IO17: U1.AE11(PB27A)
IO18: U1.AF11(PB27B)
IO19: U1.AE12(PB28B)
IO20: U1.AF12(PB28A)
IO21: U1.AF13(PB31B)
IO22: U1.AF16(PB39A)
IO23: U1.AE16(PB40A)
IO24: U1.AF17(PB41A)
IO25: U1.AE17(PB41B/D6/SPID1)
IO26: U1.AF18(PB45B)
IO27: U1.AE18(PB45A)
IO28: U1.AF19(PB47A)
IO29: U1.AE19(PB53A)
IO30: U1.AF20(PB49B)
IO31: U1.AE20(PB53B)
IO32: U1.AE21(PB50A)
IO33: U1.AE22(PB52A)
IO34: U1.AE23(PB57B)
IO35: U1.AE24(PB63A)
KBCLOCK: U1.B15(PT37B) ; port KEYBOARD.CLOCK
KBDATA: U1.A15(PT37A) ; port KEYBOARD.DATA
LED0: U1.AC6(PB5A)
LED1: U1.AD6(PB16A)
LED2: U1.AC7(PB3A)
LED3: U1.AC8(PB6B)
LED4: U1.AD8(PB10A)
LED5: U1.AC10(PB16B)
LED6: U1.AD10(PB19B)
LED7: U1.AC11(PB23B)
M0: R23.2 ; sheet U_FPGA_Power/M0
M1: R18.2 ; sheet U_FPGA_Power/M1
M2: R28.2 ; sheet U_FPGA_Power/M2
MOUSECLOCK: U1.A16(PT41A) ; port MOUSE.CLOCK
MOUSEDATA: U1.B16(PT40A) ; port MOUSE.DATA
NEXUS_TCK: U1.K21(PR25B) ; harness JTAG.TCK
NEXUS_TDI: U1.L21(PR31A/RDQS31) ; harness JTAG.TDI
NEXUS_TDO: U1.B25(PT60B) ; harness JTAG.TDO
NEXUS_TMS: U1.J20(PR24A) ; harness JTAG.TMS
ONE_WIRE_DB_PB: U1.AB11(PB24B) ; port ONE_WIRE_DB_PB
ONE_WIRE_DBID: port ONE_WIRE_DBID, sheet U_1WB_DS2406_EPROM/ONE_WIRE.ID
ONE_WIRE_PIO1: port ONE_WIRE_PIO1, sheet U_1WB_DS2406_EPROM/ONE_WIRE.PIO1
PROGRAMN: R24.2 ; sheet U_FPGA_Power/PROGRAMN
REF_CLK: U1.AE14(PB33B/PCLKC5_0) ; port CLOCKS.REF_CLK
RS232_CTS: U1.A11(PT28B) ; port RS232.CTS
RS232_RTS: U1.A10(PT26A) ; port RS232.RTS
RS232_RX: U1.B12(PT29A) ; port RS232.RXD
RS232_TX: U1.B11(PT28A) ; port RS232.TXD
SCL: U1.AA10(PB20B) ; port I2C.SCL
SDA: U1.AD9(PB12B) ; port I2C.SDA
SPI_CLK: U1.F14(PT34B) ; port SPI.CLK
SPI_DIN: U1.F13(PT30B) ; port SPI.DIN
SPI_DOUT: U1.F16(PT43B) ; port SPI.DOUT
SPI_MODE: U1.F17(PT48B) ; port SPI.MODE
SPI_SEL: U1.F15(PT38B) ; port SPI.SEL
SRAM1_A0: U1.AD21(PB60A)
SRAM1_A1: U1.AD22(PB64A)
SRAM1_A2: U1.AD23(PB63B)
SRAM1_A3: U1.AD24(PR67B)
SRAM1_A4: U1.AC24(PR68A/VREF1_3)
SRAM1_A5: U1.AA22(PR64A)
SRAM1_A6: U1.AA21(PR62A)
SRAM1_A7: U1.W22(PR55B/RLM0_PLLC_FB_A)
SRAM1_A8: U1.R21(PR42B)
SRAM1_A9: U1.N23(PR37B)
SRAM1_A10: U1.T21(PR48A/RDQS48)
SRAM1_A11: U1.U21(PR48B)
SRAM1_A12: U1.Y19(PR65A/RDQS65)
SRAM1_A13: U1.Y20(PR65B)
SRAM1_A14: U1.Y21(PR62B)
SRAM1_A15: U1.AC20(PB60B)
SRAM1_A16: U1.AD20(PB58B)
SRAM1_A17: U1.AC19(PB59A)
SRAM1_A18: U1.AB22(PB65B)
SRAM1_D0: U1.AA15(PB42B)
SRAM1_D1: U1.AA16(PB47B)
SRAM1_D2: U1.AA17(PB48A)
SRAM1_D3: U1.AB18(PB56B)
SRAM1_D4: U1.AB21(PB62A/BDQS62)
SRAM1_D5: U1.AB20(PB62B)
SRAM1_D6: U1.Y22(PR61A)
SRAM1_D7: U1.W21(PR55A/RLM0_PLLT_FB_A)
SRAM1_D8: U1.AA20(PB55B)
SRAM1_D9: U1.AB19(PB59B)
SRAM1_D10: U1.AA18(PB52B)
SRAM1_D11: U1.AB23(PR63B)
SRAM1_D12: U1.AC23(PR68B/VREF2_3)
SRAM1_D13: U1.AC22(PB65A)
SRAM1_D14: U1.AC21(PB64B)
SRAM1_D15: U1.AD17(PB43A)
SRAM1_NBHE: U1.AC18(PB56A) ; port SRAM1.NBHE
SRAM1_NBLE: U1.AC17(PB50B) ; port SRAM1.NBLE
SRAM1_NCS: U1.AA14(PB35B/CSN) ; port SRAM1.NCS
SRAM1_NOE: U1.AD19(PB58A) ; port SRAM1.NOE
SRAM1_NWE: U1.AA19(PB54A/BDQS54) ; port SRAM1.NWE
SRAM2_A0: U1.U22(PR49A)
SRAM2_A1: U1.R22(PR42A)
SRAM2_A2: U1.P22(PR40A/RDQS40)
SRAM2_A3: U1.P21(PR38A)
SRAM2_A4: U1.AB24(PR63A)
SRAM2_A5: U1.T22(PR46B)
SRAM2_A6: U1.R24(PR44A)
SRAM2_A7: U1.R23(PR45A)
SRAM2_A8: U1.P24(PR41A)
SRAM2_A9: U1.P23(PR40B)
SRAM2_A10: U1.P26(PR43A)
SRAM2_A11: U1.R26(PR43B)
SRAM2_A12: U1.R25(PR44B)
SRAM2_A13: U1.T26(PR47A)
SRAM2_A14: U1.T25(PR47B)
SRAM2_A15: U1.AD26(PR66A)
SRAM2_A16: U1.AD25(PR67A)
SRAM2_A17: U1.AE26(PR66B)
SRAM2_A18: U1.U26(PR51A)
SRAM2_D0: U1.AA24(PR60B)
SRAM2_D1: U1.Y23(PR61B)
SRAM2_D2: U1.Y24(PR60A)
SRAM2_D3: U1.W24(PR56A/RLM0_PLLT_IN_A)
SRAM2_D4: U1.W23(PR56B/RLM0_PLLC_IN_A)
SRAM2_D5: U1.U23(PR49B)
SRAM2_D6: U1.U24(PR50B)
SRAM2_D7: U1.T23(PR46A)
SRAM2_D8: U1.U25(PR50A)
SRAM2_D9: U1.V26(PR51B)
SRAM2_D10: U1.W26(PR53A/D7/SPID0)
SRAM2_D11: U1.W25(PR53B/BUSY/SISPI)
SRAM2_D12: U1.Y26(PR54A/DOUT/CSON)
SRAM2_D13: U1.AA26(PR57A/RDQS57)
SRAM2_D14: U1.AA25(PR58A)
SRAM2_D15: U1.AB26(PR57B)
SRAM2_NBHE: U1.AC26(PR59A) ; port SRAM2.NBHE
SRAM2_NBLE: U1.AB25(PR58B) ; port SRAM2.NBLE
SRAM2_NCS: U1.AA23(PR64B) ; port SRAM2.NCS
SRAM2_NOE: U1.AC25(PR59B) ; port SRAM2.NOE
SRAM2_NWE: U1.T24(PR45B) ; port SRAM2.NWE
STATUS_LED: NT6.1(Net1) ; port STATUS_LED
SW0: U1.AA11(PB26A)
SW1: U1.AB10(PB18B)
SW2: U1.AA9(PB14B)
SW3: U1.AB8(PB6A/BDQS6)
SW4: U1.AA7(PB4B)
TCK: R14.2 ; sheet U_FPGA_Power/TCK
TDI: R20.2 ; sheet U_FPGA_Power/TDI
TDO: R22.2 ; sheet U_FPGA_Power/TDO
TMS: R12.2 ; sheet U_FPGA_Power/TMS
UGCLK0: U1.B14(PT33B/PCLKC0_0)
UGCLK1: U1.N1(PL34B/PCLKC7_0)
UGCLK2: U1.N2(PL34A/PCLKT7_0)

Not connected (* = marked no-connect by the designer): U1 A7(PT20A)* A8(PT23A)* A12(PT29B)* A13(PT31B)* A17(PT41B)* A18(PT43A)* AA13(PB34A/WRITEN)* AB3(PL63B)* AB14(PB36B/D0/SPID7)* AC5(PB5B)* AC9(PB10B)* AC15(PB38B/D3/SPID4)* AD4(PB9B)* AD5(PB9A)* AD14(PB35A/VREF1_4)* AE13(PB31A)* AE25(PB61B)* B6(PT12A)* B8(PT21B)* B13(PT31A)* B17(PT50A)* B18(PT42A)* B19(PT45A)* B22(PT55A)* B23(PT62B)* B24(PT60A)* C7(PT19A)* C9(PT15A)* C13(PT32A/VREF2_0)* C18(PT53A)* D4(PT4A)* D7(PT2B)* D9(PT14A/TDQS14)* E4(PL2B/VREF1_7)* E6(PT2A)* E7(PT4B)* E8(PT7B)* E9(PT11B)* E11(PT20B)* E17(PT50B)* E21(PR6B)* F5(PL7B)* F7(PT3B)* F8(PT8B)* F19(PT55B)* G5(PL20A)* G7(PT6A/TDQS6)* G10(PT18B)* H5(PL20B)* H6(PL19A)* J5(PL23B)* J6(PL25A) J7(PL19B)* K5(PL24B)* K6(PL25B) K25(PR28B)* L5(PL33B)* L6(PL37B)* L7(PL37A)* L22(PR30B)* L25(PR29B)* L26(PR34B/PCLKC2_0)* M1(PL32A)* M6(PL41B)* M23(PR33A)* M24(PR32A)* M25(PR32B)* M26(PR39A)* N4(PL38A)* N5(PL38B)* N6(PL44A)* N21(PR38B)* N24(PR36A)* N25(PR36B)* N26(PR39B)* P2(PL36B)* P5(PL44B)* P25(PR41B)* V6(PL54A/LLM0_PLLT_FB_A)*

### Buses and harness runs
bus BUS_A[24..1]
bus BUS_D[31..0]
bus BUS_NBE[3..0]
bus DAU_TFT_BLUE[4..0]
bus DAU_TFT_CL[3..1]
bus DAU_TFT_GREEN[5..0]
bus DAU_TFT_RED[4..0]
bus DIP[7..0]
bus EXTEND_A[49..0]
bus EXTEND_B[49..0]
bus EXTEND_C[49..0]
bus FPGA_ID[3..0]
bus FPGA_M[2..0]
bus IO[35..0]
bus LED[7..0]
bus SRAM1_A[18..0]
bus SRAM1_D[15..0]
bus SRAM2_A[18..0]
bus SRAM2_D[15..0]
bus SW[4..0]

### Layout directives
net class CLKS: BUS_SDRAM_FEEDBACK, FPGA_CLK, FPGA_CLK1, REF_CLK, UGCLK0, UGCLK1, UGCLK2
net class FPGACONF: DATA_DIN, FPGA_CCLK, FPGA_DIN, FPGA_DONE, FPGA_INIT, FPGA_M0, FPGA_M1, FPGA_M2, FPGA_PROGRAM, FPGA_TCK, FPGA_TDI, FPGA_TDO, FPGA_TMS

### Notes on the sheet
- DAUGHTER BOARD I/O
- HOST PERIPHERALS
- JTAG
- PROGRAM
- Host Reset
- (near NT2) FPGA_ID = 0x3 (Lattice)
- Status LEDs
- SPI BUS
- DAUGHTER BOARD MEMORY RESOURCES
- CLOCKS
- TFT LCD DISPLAY INTERFACE
- ONE-WIRE CONNECTIONS
- NOTE: A = POSITIVE

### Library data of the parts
NT2-NT6 NT8 = D-002-0002: as NT7 on sheet PSU
R1-R4 R7 = D-100-0088: Resistor, 4K7 1% 0402 (1005); Power Rating: 63 mW; Resistance: 4.7 K
R8 R12 R14 R18 R20 R22-R28 = D-100-0131: Resistor, 100R 1% 0402 (1005); Power Rating: 63 mW
U1 = D-241-0003: FPGA, Lattice ECP-35 FN672; Supply Voltage: mV

## Sheet FPGA_NonIO.SchDoc: FPGA Power and Programming
size A4; Organization: Altium Limited.; Address1: Level 3, 12a Rodborough Rd; Address2: Frenchs Forest 2086; Address3: NSW; Address4: AUSTRALIA; DocumentNumber: 7; SheetNumber: 7; SheetTotal: 21; PageSetup: Record=PageOptions|CenterHorizontal=True|CenterVertical=True|PrintScale=0.97|XCorrection=1.00|YCorrection=1.00|PrintKind=2|BorderSize=5000000|LeftOffset=0|BottomOffset=0|Orientation=2|PaperLength=1000|PaperWidth=1000|Scale=100|PaperSource=15|PrintQuality=600|MediaType=1|DitherType=10|PaperKind=A4|PrintScaleMode=1
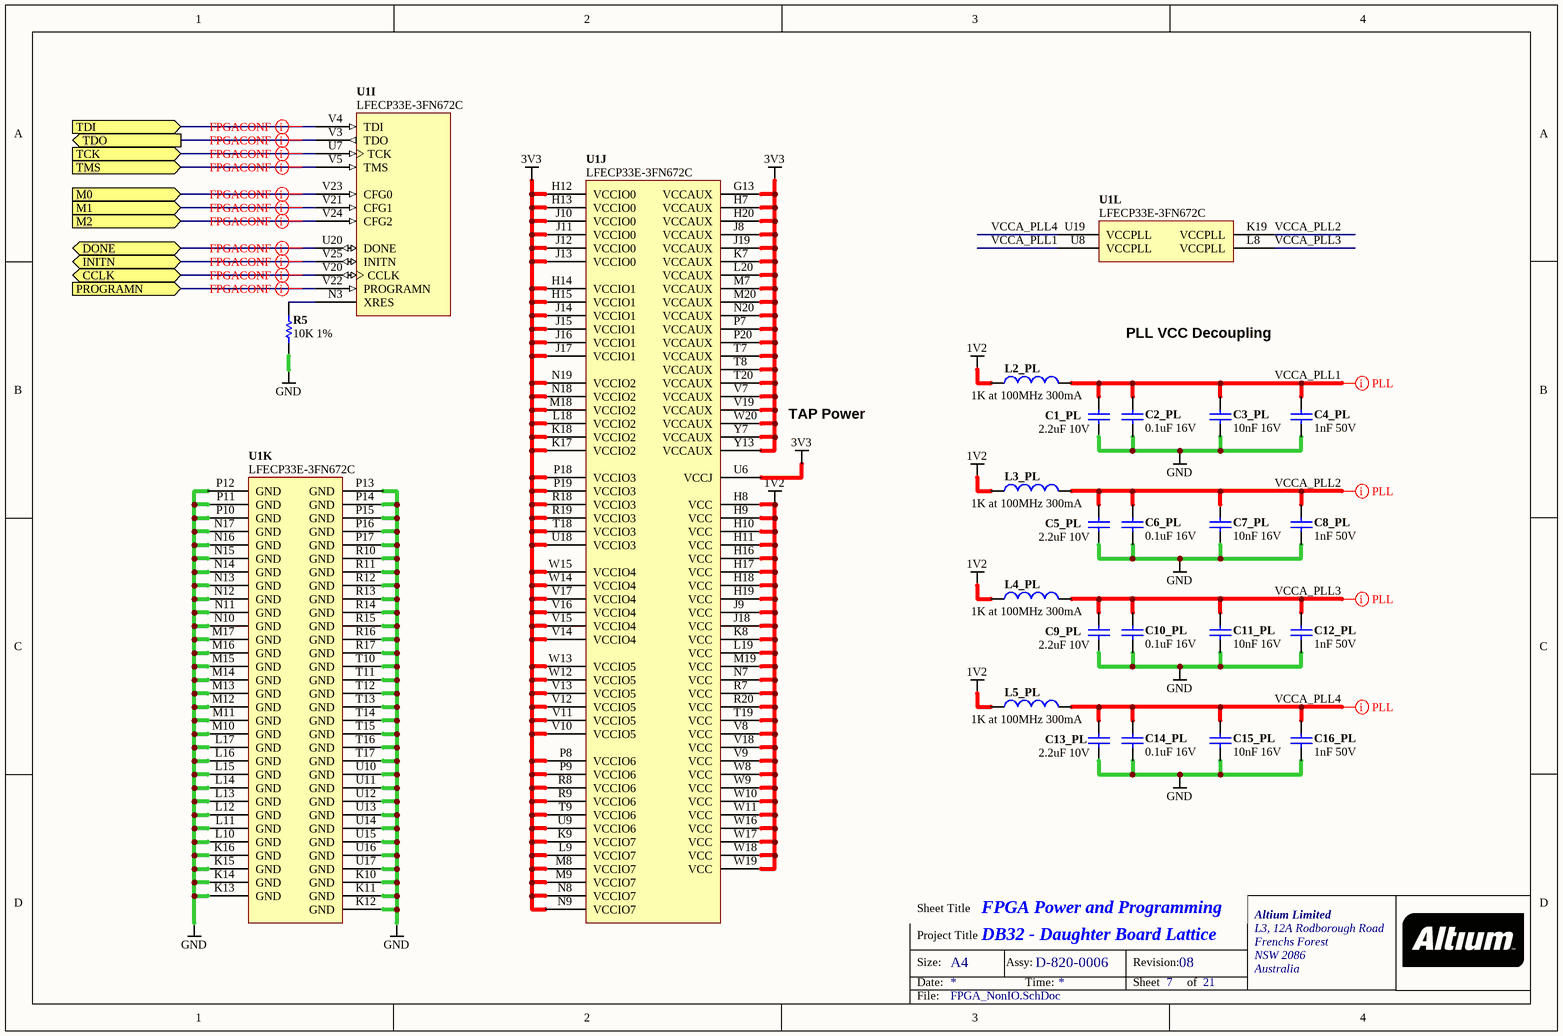
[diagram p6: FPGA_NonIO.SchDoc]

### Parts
C1_PL  2.2uF 10V  [CAPC1608-STAR]
C2_PL  0.1uF 16V  [CAPC1005-STAR]
C3_PL  10nF 16V  [CAPC1005-STAR]
C4_PL  1nF 50V  [CAPC1005-STAR]
C5_PL  2.2uF 10V  [CAPC1608-STAR]
C6_PL  0.1uF 16V  [CAPC1005-STAR]
C7_PL  10nF 16V  [CAPC1005-STAR]
C8_PL  1nF 50V  [CAPC1005-STAR]
C9_PL  2.2uF 10V  [CAPC1608-STAR]
C10_PL  0.1uF 16V  [CAPC1005-STAR]
C11_PL  10nF 16V  [CAPC1005-STAR]
C12_PL  1nF 50V  [CAPC1005-STAR]
C13_PL  2.2uF 10V  [CAPC1608-STAR]
C14_PL  0.1uF 16V  [CAPC1005-STAR]
C15_PL  10nF 16V  [CAPC1005-STAR]
C16_PL  1nF 50V  [CAPC1005-STAR]
L2_PL  1K at 100MHz 300mA  [INDC2012-STAR]
L3_PL  1K at 100MHz 300mA  [INDC2012-STAR]
L4_PL  1K at 100MHz 300mA  [INDC2012-STAR]
L5_PL  1K at 100MHz 300mA  [INDC2012-STAR]
R5  10K 1%  [RESC1005-STAR]
U1  LFECP33E-3FN672C  [BGA100P26X26-672]  (parts I,J,K,L of 12)

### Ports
CCLK (bidir), DONE (bidir), INITN (bidir), M0 (in), M1 (in), M2 (in), PROGRAMN (in), TCK (in), TDI (in), TDO (out), TMS (in)

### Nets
1V2: L2_PL.1 L3_PL.1 L4_PL.1 L5_PL.1 U1.H8(VCC) U1.H9(VCC) U1.H10(VCC) U1.H11(VCC) U1.H16(VCC) U1.H17(VCC) U1.H18(VCC) U1.H19(VCC) U1.J9(VCC) U1.J18(VCC) U1.K8(VCC) U1.L19(VCC) U1.M19(VCC) U1.N7(VCC) U1.R7(VCC) U1.R20(VCC) U1.T19(VCC) U1.V8(VCC) U1.V9(VCC) U1.V18(VCC) U1.W8(VCC) U1.W9(VCC) U1.W10(VCC) U1.W11(VCC) U1.W16(VCC) U1.W17(VCC) U1.W18(VCC) U1.W19(VCC)
3V3: U1.G13(VCCAUX) U1.H7(VCCAUX) U1.H12(VCCIO0) U1.H13(VCCIO0) U1.H14(VCCIO1) U1.H15(VCCIO1) U1.H20(VCCAUX) U1.J8(VCCAUX) U1.J10(VCCIO0) U1.J11(VCCIO0) U1.J12(VCCIO0) U1.J13(VCCIO0) U1.J14(VCCIO1) U1.J15(VCCIO1) U1.J16(VCCIO1) U1.J17(VCCIO1) U1.J19(VCCAUX) U1.K7(VCCAUX) U1.K9(VCCIO7) U1.K17(VCCIO2) U1.K18(VCCIO2) U1.L9(VCCIO7) U1.L18(VCCIO2) U1.L20(VCCAUX) U1.M7(VCCAUX) U1.M8(VCCIO7) U1.M9(VCCIO7) U1.M18(VCCIO2) U1.M20(VCCAUX) U1.N8(VCCIO7) U1.N9(VCCIO7) U1.N18(VCCIO2) U1.N19(VCCIO2) U1.N20(VCCAUX) U1.P7(VCCAUX) U1.P8(VCCIO6) U1.P9(VCCIO6) U1.P18(VCCIO3) U1.P19(VCCIO3) U1.P20(VCCAUX) U1.R8(VCCIO6) U1.R9(VCCIO6) U1.R18(VCCIO3) U1.R19(VCCIO3) U1.T7(VCCAUX) U1.T8(VCCAUX) U1.T9(VCCIO6) U1.T18(VCCIO3) U1.T20(VCCAUX) U1.U6(VCCJ) U1.U9(VCCIO6) U1.U18(VCCIO3) U1.V7(VCCAUX) U1.V10(VCCIO5) U1.V11(VCCIO5) U1.V12(VCCIO5) U1.V13(VCCIO5) U1.V14(VCCIO4) U1.V15(VCCIO4) U1.V16(VCCIO4) U1.V17(VCCIO4) U1.V19(VCCAUX) U1.W12(VCCIO5) U1.W13(VCCIO5) U1.W14(VCCIO4) U1.W15(VCCIO4) U1.W20(VCCAUX) U1.Y7(VCCAUX) U1.Y13(VCCAUX)
GND: C1_PL.2 C2_PL.2 C3_PL.2 C4_PL.2 C5_PL.2 C6_PL.2 C7_PL.2 C8_PL.2 C9_PL.2 C10_PL.2 C11_PL.2 C12_PL.2 C13_PL.2 C14_PL.2 C15_PL.2 C16_PL.2 R5.2 U1.K10(GND) U1.K11(GND) U1.K12(GND) U1.K13(GND) U1.K14(GND) U1.K15(GND) U1.K16(GND) U1.L10(GND) U1.L11(GND) U1.L12(GND) U1.L13(GND) U1.L14(GND) U1.L15(GND) U1.L16(GND) U1.L17(GND) U1.M10(GND) U1.M11(GND) U1.M12(GND) U1.M13(GND) U1.M14(GND) U1.M15(GND) U1.M16(GND) U1.M17(GND) U1.N10(GND) U1.N11(GND) U1.N12(GND) U1.N13(GND) U1.N14(GND) U1.N15(GND) U1.N16(GND) U1.N17(GND) U1.P10(GND) U1.P11(GND) U1.P12(GND) U1.P13(GND) U1.P14(GND) U1.P15(GND) U1.P16(GND) U1.P17(GND) U1.R10(GND) U1.R11(GND) U1.R12(GND) U1.R13(GND) U1.R14(GND) U1.R15(GND) U1.R16(GND) U1.R17(GND) U1.T10(GND) U1.T11(GND) U1.T12(GND) U1.T13(GND) U1.T14(GND) U1.T15(GND) U1.T16(GND) U1.T17(GND) U1.U10(GND) U1.U11(GND) U1.U12(GND) U1.U13(GND) U1.U14(GND) U1.U15(GND) U1.U16(GND) U1.U17(GND)
CCLK: U1.V20(CCLK) ; port CCLK
DONE: U1.U20(DONE) ; port DONE
INITN: U1.V25(INITN) ; port INITN
M0: U1.V23(CFG0) ; port M0
M1: U1.V21(CFG1) ; port M1
M2: U1.V24(CFG2) ; port M2
PROGRAMN: U1.V22(PROGRAMN) ; port PROGRAMN
TCK: U1.U7(TCK) ; port TCK
TDI: U1.V4(TDI) ; port TDI
TDO: U1.V3(TDO) ; port TDO
TMS: U1.V5(TMS) ; port TMS
VCCA_PLL1: C1_PL.1 C2_PL.1 C3_PL.1 C4_PL.1 L2_PL.2 U1.U8(VCCPLL)
VCCA_PLL2: C5_PL.1 C6_PL.1 C7_PL.1 C8_PL.1 L3_PL.2 U1.K19(VCCPLL)
VCCA_PLL3: C9_PL.1 C10_PL.1 C11_PL.1 C12_PL.1 L4_PL.2 U1.L8(VCCPLL)
VCCA_PLL4: C13_PL.1 C14_PL.1 C15_PL.1 C16_PL.1 L5_PL.2 U1.U19(VCCPLL)
NetR5_1: R5.1 U1.N3(XRES)

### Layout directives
net class FPGACONF: CCLK, DONE, INITN, M0, M1, M2, PROGRAMN, TCK, TDI, TDO, TMS
net class PLL: VCCA_PLL1, VCCA_PLL2, VCCA_PLL3, VCCA_PLL4

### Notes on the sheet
- PLL VCC Decoupling
- TAP Power

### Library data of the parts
C1_PL C5_PL C9_PL C13_PL = D-101-0095: Capacitor, Ceramic, 2.2uF 10% 10V 0603 (1608) X5R; Polarity: Non-Polarized
C2_PL C6_PL C10_PL C14_PL = D-101-0080: Capacitor, Ceramic, 0.1uF 10% 16V 0402 (1005) X7R; Polarity: Non-Polarized
C3_PL C7_PL C11_PL C15_PL = D-101-0077: Capacitor, Ceramic, 10nF 10% 16V 0402 (1005) X7R; Polarity: Non-Polarized
C4_PL C8_PL C12_PL C16_PL = D-101-0030: Capacitor, Ceramic, 1nF 10% 50V 0402 (1005) X7R; Polarity: Non-Polarized
L2_PL L3_PL L4_PL L5_PL = D-102-0002: Inductor, Ferrite Bead 1K@100MHz 300mA 0805 (2012) BMB2A1000LN2; Inductance: nH
R5 = D-100-0130: Resistor, 10K 1% 0402 (1005); Power Rating: 63 mW
U1 = D-241-0003: as U1 on sheet FPGA

## Sheet Bypass_FPGA_3V3.SchDoc: FPGA Bypass Capacitors for 3V3
size A4; Organization: Altium Limited.; Address1: Level 3, 12a Rodborough Rd; Address2: Frenchs Forest 2086; Address3: NSW; Address4: AUSTRALIA; DocumentNumber: 6; SheetNumber: 6; SheetTotal: 21; PageSetup: Record=PageOptions|CenterHorizontal=True|CenterVertical=True|PrintScale=0.97|XCorrection=1.00|YCorrection=1.00|PrintKind=1|BorderSize=5000000|LeftOffset=0|BottomOffset=0|Orientation=2|PaperLength=1000|PaperWidth=1000|Scale=100|PaperSource=262|PrintQuality=600|MediaType=1|DitherType=10|PaperKind=A4|PrintScaleMode=1
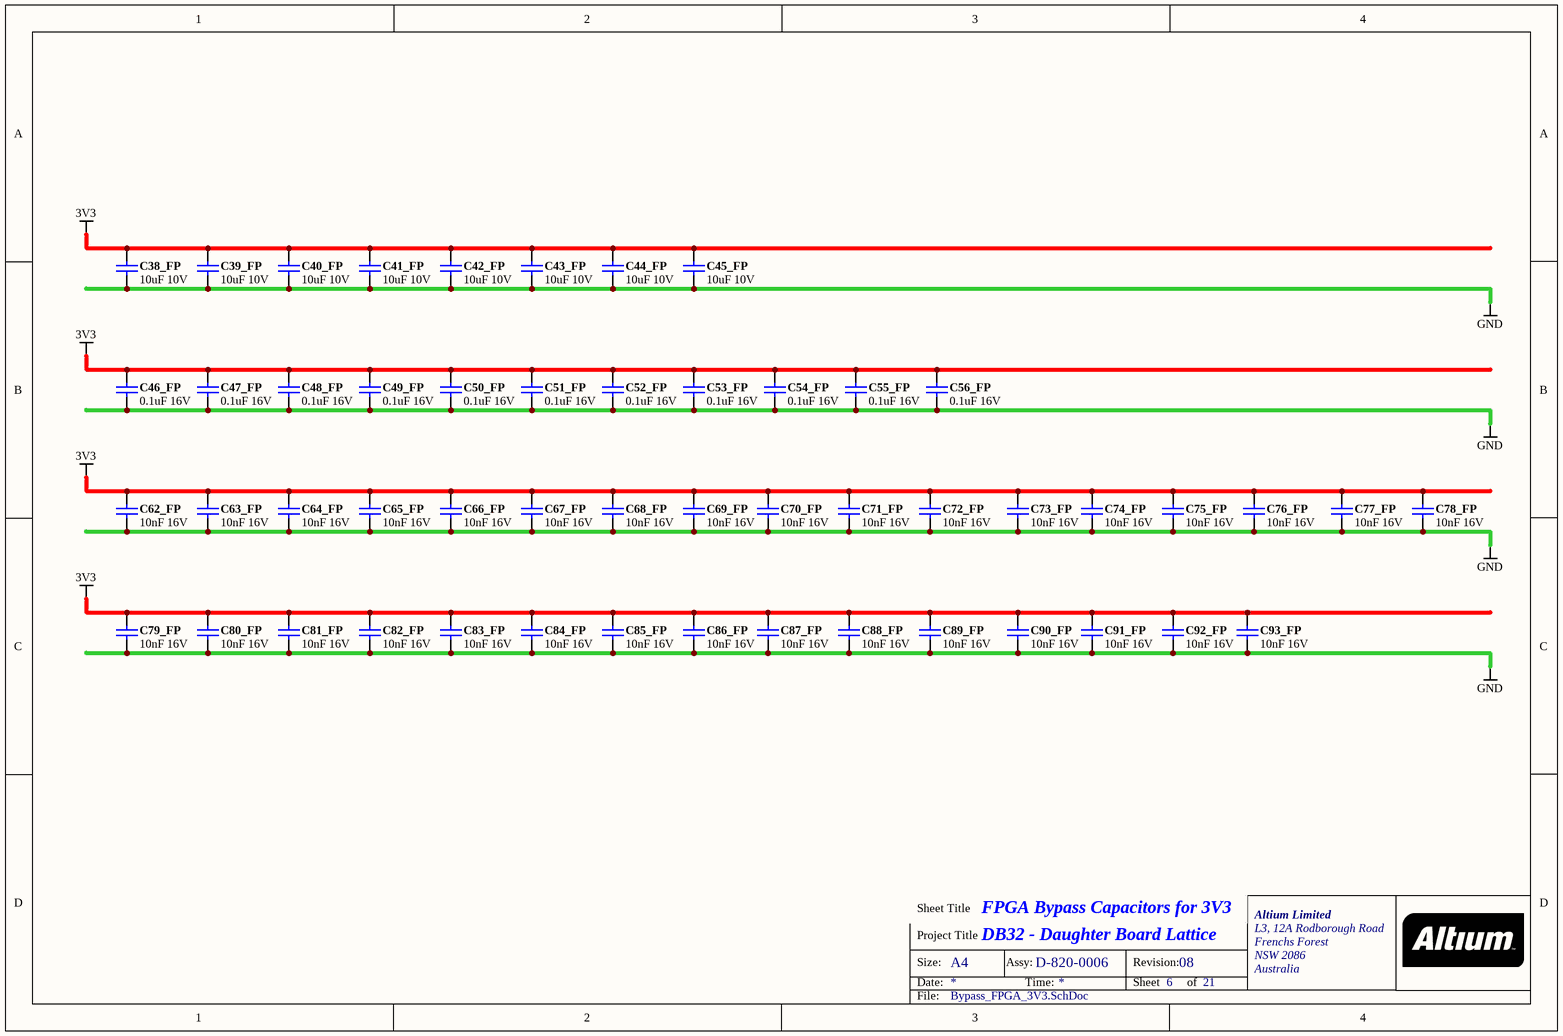
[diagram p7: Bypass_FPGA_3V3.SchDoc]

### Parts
C38_FP  10uF 10V  [CAPC2012-STAR]
C39_FP  10uF 10V  [CAPC2012-STAR]
C40_FP  10uF 10V  [CAPC2012-STAR]
C41_FP  10uF 10V  [CAPC2012-STAR]
C42_FP  10uF 10V  [CAPC2012-STAR]
C43_FP  10uF 10V  [CAPC2012-STAR]
C44_FP  10uF 10V  [CAPC2012-STAR]
C45_FP  10uF 10V  [CAPC2012-STAR]
C46_FP  0.1uF 16V  [CAPC1005-STAR]
C47_FP  0.1uF 16V  [CAPC1005-STAR]
C48_FP  0.1uF 16V  [CAPC1005-STAR]
C49_FP  0.1uF 16V  [CAPC1005-STAR]
C50_FP  0.1uF 16V  [CAPC1005-STAR]
C51_FP  0.1uF 16V  [CAPC1005-STAR]
C52_FP  0.1uF 16V  [CAPC1005-STAR]
C53_FP  0.1uF 16V  [CAPC1005-STAR]
C54_FP  0.1uF 16V  [CAPC1005-STAR]
C55_FP  0.1uF 16V  [CAPC1005-STAR]
C56_FP  0.1uF 16V  [CAPC1005-STAR]
C62_FP  10nF 16V  [CAPC1005-STAR]
C63_FP  10nF 16V  [CAPC1005-STAR]
C64_FP  10nF 16V  [CAPC1005-STAR]
C65_FP  10nF 16V  [CAPC1005-STAR]
C66_FP  10nF 16V  [CAPC1005-STAR]
C67_FP  10nF 16V  [CAPC1005-STAR]
C68_FP  10nF 16V  [CAPC1005-STAR]
C69_FP  10nF 16V  [CAPC1005-STAR]
C70_FP  10nF 16V  [CAPC1005-STAR]
C71_FP  10nF 16V  [CAPC1005-STAR]
C72_FP  10nF 16V  [CAPC1005-STAR]
C73_FP  10nF 16V  [CAPC1005-STAR]
C74_FP  10nF 16V  [CAPC1005-STAR]
C75_FP  10nF 16V  [CAPC1005-STAR]
C76_FP  10nF 16V  [CAPC1005-STAR]
C77_FP  10nF 16V  [CAPC1005-STAR]
C78_FP  10nF 16V  [CAPC1005-STAR]
C79_FP  10nF 16V  [CAPC1005-STAR]
C80_FP  10nF 16V  [CAPC1005-STAR]
C81_FP  10nF 16V  [CAPC1005-STAR]
C82_FP  10nF 16V  [CAPC1005-STAR]
C83_FP  10nF 16V  [CAPC1005-STAR]
C84_FP  10nF 16V  [CAPC1005-STAR]
C85_FP  10nF 16V  [CAPC1005-STAR]
C86_FP  10nF 16V  [CAPC1005-STAR]
C87_FP  10nF 16V  [CAPC1005-STAR]
C88_FP  10nF 16V  [CAPC1005-STAR]
C89_FP  10nF 16V  [CAPC1005-STAR]
C90_FP  10nF 16V  [CAPC1005-STAR]
C91_FP  10nF 16V  [CAPC1005-STAR]
C92_FP  10nF 16V  [CAPC1005-STAR]
C93_FP  10nF 16V  [CAPC1005-STAR]

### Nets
3V3: C38_FP.1 C39_FP.1 C40_FP.1 C41_FP.1 C42_FP.1 C43_FP.1 C44_FP.1 C45_FP.1 C46_FP.1 C47_FP.1 C48_FP.1 C49_FP.1 C50_FP.1 C51_FP.1 C52_FP.1 C53_FP.1 C54_FP.1 C55_FP.1 C56_FP.1 C62_FP.1 C63_FP.1 C64_FP.1 C65_FP.1 C66_FP.1 C67_FP.1 C68_FP.1 C69_FP.1 C70_FP.1 C71_FP.1 C72_FP.1 C73_FP.1 C74_FP.1 C75_FP.1 C76_FP.1 C77_FP.1 C78_FP.1 C79_FP.1 C80_FP.1 C81_FP.1 C82_FP.1 C83_FP.1 C84_FP.1 C85_FP.1 C86_FP.1 C87_FP.1 C88_FP.1 C89_FP.1 C90_FP.1 C91_FP.1 C92_FP.1 C93_FP.1
GND: C38_FP.2 C39_FP.2 C40_FP.2 C41_FP.2 C42_FP.2 C43_FP.2 C44_FP.2 C45_FP.2 C46_FP.2 C47_FP.2 C48_FP.2 C49_FP.2 C50_FP.2 C51_FP.2 C52_FP.2 C53_FP.2 C54_FP.2 C55_FP.2 C56_FP.2 C62_FP.2 C63_FP.2 C64_FP.2 C65_FP.2 C66_FP.2 C67_FP.2 C68_FP.2 C69_FP.2 C70_FP.2 C71_FP.2 C72_FP.2 C73_FP.2 C74_FP.2 C75_FP.2 C76_FP.2 C77_FP.2 C78_FP.2 C79_FP.2 C80_FP.2 C81_FP.2 C82_FP.2 C83_FP.2 C84_FP.2 C85_FP.2 C86_FP.2 C87_FP.2 C88_FP.2 C89_FP.2 C90_FP.2 C91_FP.2 C92_FP.2 C93_FP.2

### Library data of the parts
C38_FP C39_FP C40_FP C41_FP C42_FP C43_FP C44_FP C45_FP = D-101-0087: as C23_CM on sheet PSU
C46_FP C47_FP C48_FP C49_FP C50_FP C51_FP C52_FP C53_FP C54_FP C55_FP C56_FP = D-101-0080: as C2_PL on sheet FPGA_NonIO
C62_FP C63_FP C64_FP C65_FP C66_FP C67_FP C68_FP C69_FP C70_FP C71_FP C72_FP C73_FP C74_FP C75_FP C76_FP C77_FP C78_FP C79_FP C80_FP C81_FP C82_FP C83_FP C84_FP C85_FP C86_FP C87_FP C88_FP C89_FP C90_FP C91_FP C92_FP C93_FP = D-101-0077: as C3_PL on sheet FPGA_NonIO

## Sheet Bypass_FPGA_1V2.SCHDOC: FPGA Bypass Capacitors for 1V2
size A4; Organization: Altium Limited.; Address1: Level 3, 12a Rodborough Rd; Address2: Frenchs Forest 2086; Address3: NSW; Address4: AUSTRALIA; DocumentNumber: 5; SheetNumber: 5; SheetTotal: 21
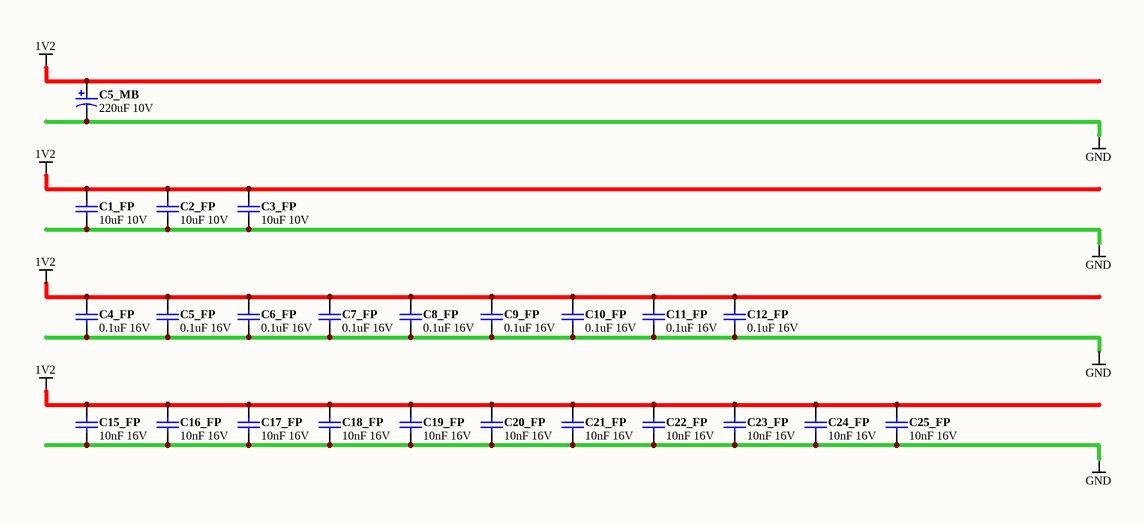
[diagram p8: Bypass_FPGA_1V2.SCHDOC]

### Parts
C1_FP  10uF 10V  [CAPC2012-STAR]
C2_FP  10uF 10V  [CAPC2012-STAR]
C3_FP  10uF 10V  [CAPC2012-STAR]
C4_FP  0.1uF 16V  [CAPC1005-STAR]
C5_FP  0.1uF 16V  [CAPC1005-STAR]
C5_MB  220uF 10V  [CAPC7343-STAR]
C6_FP  0.1uF 16V  [CAPC1005-STAR]
C7_FP  0.1uF 16V  [CAPC1005-STAR]
C8_FP  0.1uF 16V  [CAPC1005-STAR]
C9_FP  0.1uF 16V  [CAPC1005-STAR]
C10_FP  0.1uF 16V  [CAPC1005-STAR]
C11_FP  0.1uF 16V  [CAPC1005-STAR]
C12_FP  0.1uF 16V  [CAPC1005-STAR]
C15_FP  10nF 16V  [CAPC1005-STAR]
C16_FP  10nF 16V  [CAPC1005-STAR]
C17_FP  10nF 16V  [CAPC1005-STAR]
C18_FP  10nF 16V  [CAPC1005-STAR]
C19_FP  10nF 16V  [CAPC1005-STAR]
C20_FP  10nF 16V  [CAPC1005-STAR]
C21_FP  10nF 16V  [CAPC1005-STAR]
C22_FP  10nF 16V  [CAPC1005-STAR]
C23_FP  10nF 16V  [CAPC1005-STAR]
C24_FP  10nF 16V  [CAPC1005-STAR]
C25_FP  10nF 16V  [CAPC1005-STAR]

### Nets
1V2: C1_FP.1 C2_FP.1 C3_FP.1 C4_FP.1 C5_FP.1 C5_MB.1 C6_FP.1 C7_FP.1 C8_FP.1 C9_FP.1 C10_FP.1 C11_FP.1 C12_FP.1 C15_FP.1 C16_FP.1 C17_FP.1 C18_FP.1 C19_FP.1 C20_FP.1 C21_FP.1 C22_FP.1 C23_FP.1 C24_FP.1 C25_FP.1
GND: C1_FP.2 C2_FP.2 C3_FP.2 C4_FP.2 C5_FP.2 C5_MB.2 C6_FP.2 C7_FP.2 C8_FP.2 C9_FP.2 C10_FP.2 C11_FP.2 C12_FP.2 C15_FP.2 C16_FP.2 C17_FP.2 C18_FP.2 C19_FP.2 C20_FP.2 C21_FP.2 C22_FP.2 C23_FP.2 C24_FP.2 C25_FP.2

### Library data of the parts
C1_FP C2_FP C3_FP = D-101-0087: as C23_CM on sheet PSU
C4_FP C5_FP C6_FP C7_FP C8_FP C9_FP C10_FP C11_FP C12_FP = D-101-0080: as C2_PL on sheet FPGA_NonIO
C5_MB = D-101-0088: Capacitor, Tantalum, 220uF 10% 10V MCCT-D (7343-31); Polarity: Polarized
C15_FP C16_FP C17_FP C18_FP C19_FP C20_FP C21_FP C22_FP C23_FP C24_FP C25_FP = D-101-0077: as C3_PL on sheet FPGA_NonIO

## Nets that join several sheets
1V2: PSU (TP4.1), FPGA_NonIO (32 pins), Bypass_FPGA_1V2 (24 pins)
3V3: PSU (C23_CM.1 C24_CM.1 TP1.1), FPGA (7 pins), FPGA_NonIO (69 pins), Bypass_FPGA_3V3 (51 pins)
GND: PSU (5 pins), FPGA (NT4.2 NT5.2), FPGA_NonIO (80 pins), Bypass_FPGA_3V3 (51 pins), Bypass_FPGA_1V2 (24 pins)
CCLK: FPGA (R26.2), FPGA_NonIO (U1.V20)
DONE: FPGA (R25.2), FPGA_NonIO (U1.U20)
INITN: FPGA (R8.2), FPGA_NonIO (U1.V25)
M0: FPGA (R23.2), FPGA_NonIO (U1.V23)
M1: FPGA (R18.2), FPGA_NonIO (U1.V21)
M2: FPGA (R28.2), FPGA_NonIO (U1.V24)
PROGRAMN: FPGA (R24.2), FPGA_NonIO (U1.V22)
TCK: FPGA (R14.2), FPGA_NonIO (U1.U7)
TDI: FPGA (R20.2), FPGA_NonIO (U1.V4)
TDO: FPGA (R22.2), FPGA_NonIO (U1.V3)
TMS: FPGA (R12.2), FPGA_NonIO (U1.V5)

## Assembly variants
Production: not fitted RN1 RN2 RN3 RN4 RN5 RN6 RN7 RN8 RN17 RN18 RN19 RN20 RN21 RN22 RN23 RN24 RN25 RN26 RN27 RN28 RN29 RN30 RN31 RN32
